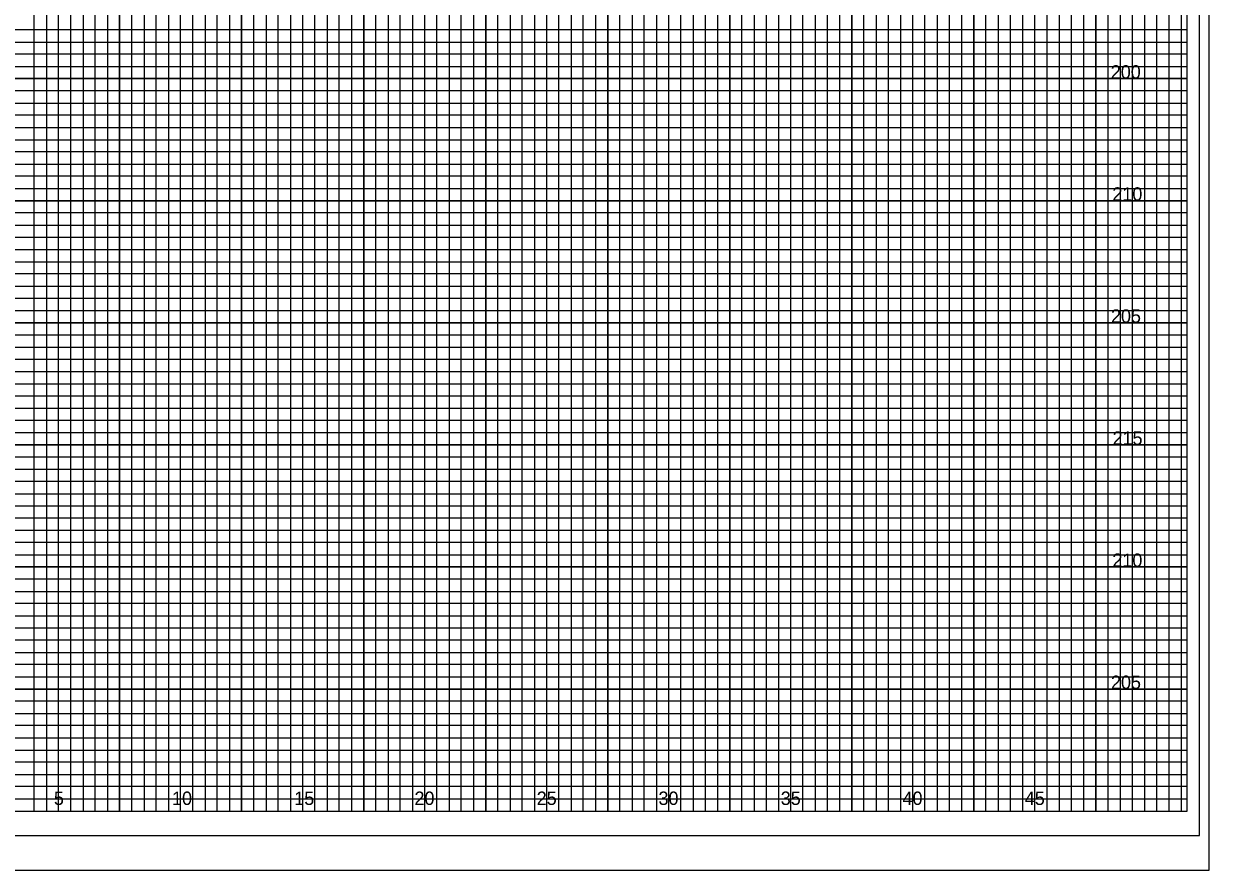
# Model space of a CAD drawing. Extents: x -4 to 103, y -2 to 67.
# Drawn here: x 54.82 to 103.4, y -2.43 to 32.25 of the extents above; entities that cross this region are included whole.
import ezdxf

# ---------------------------------------------------------------- set-up
doc = ezdxf.new("R2010")
doc.units = 0
for name, color, linetype in [('Old_Level_10', 7, 'Continuous'), ('Old_Level_16', 7, 'Continuous'), ('Old_Level_17', 7, 'Continuous'), ('Old_Level_3', 7, 'Continuous'), ('Old_Level_5', 7, 'Continuous'), ('Old_Level_8', 7, 'Continuous'), ('Prop Plan Preparation Sketches Hydraulic Ditch', 7, 'Continuous'), ('Prop XS Dump Level', 7, 'Continuous'), ('Prop XS Finish Grade Pavement', 7, 'Continuous')]:
    doc.layers.add(name, color=color, linetype=linetype)

msp = doc.modelspace()

# ---------------------------------------------------------------- linework, layer by layer
at = {"layer": 'Old_Level_10'}
for p, q in [((56.25, 0), (56.25, 65)), ((58.75, 0), (58.75, 65)), ((61.25, 0), (61.25, 65)), ((63.75, 0), (63.75, 65)), ((66.25, 0), (66.25, 65)), ((68.75, 0), (68.75, 65)), ((71.25, 0), (71.25, 65)), ((73.75, 0), (73.75, 65)), ((91.25, 0), (91.25, 63.425)), ((93.75, 0), (93.75, 63.425)), ((96.25, 0), (96.25, 63.425)), ((98.75, 0), (98.75, 63.425)), ((101.25, 0), (101.25, 63.425)), ((76.25, 0), (76.25, 62)), ((78.75, 0), (78.75, 62)), ((81.25, 0), (81.25, 62)), ((83.75, 0), (83.75, 62)), ((86.25, 0), (86.25, 62)), ((88.75, 0), (88.75, 62)), ((0, 30), (102.5, 30)), ((0, 27.5), (102.5, 27.5)), ((0, 25), (102.5, 25)), ((0, 22.5), (102.5, 22.5)), ((0, 20), (102.5, 20)), ((0, 17.5), (102.5, 17.5)), ((0, 15), (102.5, 15)), ((0, 12.5), (102.5, 12.5)), ((0, 10), (102.5, 10)), ((0, 7.5), (102.5, 7.5)), ((0, 5), (102.5, 5)), ((0, 2.5), (102.5, 2.5))]:
    msp.add_line(p, q, dxfattribs=at)
at = {"layer": 'Old_Level_17'}
msp.add_lwpolyline([(103, 66), (-2.8, 66), (-2.8, -1), (103, -1)], close=True, dxfattribs=at)
at = {"layer": 'Old_Level_3'}
msp.add_line((-3.5, -2.425), (103.4, -2.425), dxfattribs=at)
at = {"layer": 'Old_Level_5'}
msp.add_lwpolyline([(103.4, 67.4), (-3.5, 67.4), (-3.5, -2.425), (103.4, -2.425)], close=True, dxfattribs=at)
at = {"layer": 'Old_Level_8'}
for points in [[(56.25, 0), (56.25, 65)], [(58.75, 65), (58.75, 0), (61.25, 0), (61.25, 65)], [(63.75, 65), (63.75, 0), (66.25, 0), (66.25, 65)], [(68.75, 65), (68.75, 0), (71.25, 0), (71.25, 65)], [(73.75, 65), (73.75, 0), (76.25, 0), (76.25, 62)], [(88.75, 62), (88.75, 0), (91.25, 0), (91.25, 63.425)], [(93.75, 63.425), (93.75, 0), (96.25, 0), (96.25, 63.425)], [(98.75, 63.425), (98.75, 0), (101.25, 0), (101.25, 63.425)], [(78.75, 62), (78.75, 0), (81.25, 0), (81.25, 62)], [(83.75, 62), (83.75, 0), (86.25, 0), (86.25, 62)], [(0, 27.5), (102.5, 27.5), (102.5, 30), (0, 30)], [(0, 22.5), (102.5, 22.5), (102.5, 25), (0, 25)], [(0, 17.5), (102.5, 17.5), (102.5, 20), (0, 20)], [(0, 12.5), (102.5, 12.5), (102.5, 15), (0, 15)], [(0, 7.5), (102.5, 7.5), (102.5, 10), (0, 10)], [(0, 2.5), (102.5, 2.5), (102.5, 5), (0, 5)]]:
    msp.add_lwpolyline(points, dxfattribs=at)
at = {"layer": 'Prop Plan Preparation Sketches Hydraulic Ditch'}
msp.add_lwpolyline([(102.5, 65), (0, 65), (0, 0), (102.5, 0)], close=True, dxfattribs=at)
at = {"layer": 'Prop XS Dump Level'}
for points in [[(54.75, 0), (55.25, 0), (55.25, 65)], [(55.75, 65), (55.75, 0), (56.75, 0), (56.75, 65)], [(57.25, 65), (57.25, 0), (57.75, 0), (57.75, 65)], [(58.25, 65), (58.25, 0), (59.25, 0), (59.25, 65)], [(59.75, 65), (59.75, 0), (60.25, 0), (60.25, 65)], [(60.75, 65), (60.75, 0), (61.75, 0), (61.75, 65)], [(62.25, 65), (62.25, 0), (62.75, 0), (62.75, 65)], [(63.25, 65), (63.25, 0), (64.25, 0), (64.25, 65)], [(64.75, 65), (64.75, 0), (65.25, 0), (65.25, 65)], [(65.75, 65), (65.75, 0), (66.75, 0), (66.75, 65)], [(67.25, 65), (67.25, 0), (67.75, 0), (67.75, 65)], [(68.25, 65), (68.25, 0), (69.25, 0), (69.25, 65)], [(69.75, 65), (69.75, 0), (70.25, 0), (70.25, 65)], [(70.75, 65), (70.75, 0), (71.75, 0), (71.75, 65)], [(72.25, 65), (72.25, 0), (72.75, 0), (72.75, 65)], [(73.25, 65), (73.25, 0), (74.25, 0), (74.25, 62)], [(89.75, 62), (89.75, 0), (90.25, 0), (90.25, 63.425)], [(90.75, 63.425), (90.75, 0), (91.75, 0), (91.75, 63.425)], [(92.25, 63.425), (92.25, 0), (92.75, 0), (92.75, 63.425)], [(93.25, 63.425), (93.25, 0), (94.25, 0), (94.25, 63.425)], [(94.75, 63.425), (94.75, 0), (95.25, 0), (95.25, 63.425)], [(95.75, 63.425), (95.75, 0), (96.75, 0), (96.75, 63.425)], [(97.25, 63.425), (97.25, 0), (97.75, 0), (97.75, 63.425)], [(98.25, 63.425), (98.25, 0), (99.25, 0), (99.25, 63.425)], [(99.75, 63.425), (99.75, 0), (100.25, 0), (100.25, 63.425)], [(100.25, 63.425), (100.75, 63.425), (100.75, 0), (101.75, 0), (101.75, 63.425), (102.25, 63.425), (102.25, 0)], [(74.75, 62), (74.75, 0), (75.25, 0), (75.25, 62)], [(75.75, 62), (75.75, 0), (76.75, 0), (76.75, 62)], [(77.25, 62), (77.25, 0), (77.75, 0), (77.75, 62)], [(78.25, 62), (78.25, 0), (79.25, 0), (79.25, 62)], [(79.75, 62), (79.75, 0), (80.25, 0), (80.25, 62)], [(80.75, 62), (80.75, 0), (81.75, 0), (81.75, 62)], [(82.25, 62), (82.25, 0), (82.75, 0), (82.75, 62)], [(83.25, 62), (83.25, 0), (84.25, 0), (84.25, 62)], [(84.75, 62), (84.75, 0), (85.25, 0), (85.25, 62)], [(85.75, 62), (85.75, 0), (86.75, 0), (86.75, 62)], [(87.25, 62), (87.25, 0), (87.75, 0), (87.75, 62)], [(88.25, 62), (88.25, 0), (89.25, 0), (89.25, 62)], [(0, 31.5), (102.5, 31.5), (102.5, 32), (0, 32)], [(0, 30.5), (102.5, 30.5), (102.5, 31), (0, 31)], [(0, 29), (102.5, 29), (102.5, 29.5), (0, 29.5)], [(0, 28), (102.5, 28), (102.5, 28.5), (0, 28.5)], [(0, 26.5), (102.5, 26.5), (102.5, 27), (0, 27)], [(0, 25.5), (102.5, 25.5), (102.5, 26), (0, 26)], [(0, 24), (102.5, 24), (102.5, 24.5), (0, 24.5)], [(0, 23), (102.5, 23), (102.5, 23.5), (0, 23.5)], [(0, 21.5), (102.5, 21.5), (102.5, 22), (0, 22)], [(0, 20.5), (102.5, 20.5), (102.5, 21), (0, 21)], [(0, 19), (102.5, 19), (102.5, 19.5), (0, 19.5)], [(0, 18), (102.5, 18), (102.5, 18.5), (0, 18.5)], [(0, 16.5), (102.5, 16.5), (102.5, 17), (0, 17)], [(0, 15.5), (102.5, 15.5), (102.5, 16), (0, 16)], [(0, 14), (102.5, 14), (102.5, 14.5), (0, 14.5)], [(0, 13), (102.5, 13), (102.5, 13.5), (0, 13.5)], [(0, 11.5), (102.5, 11.5), (102.5, 12), (0, 12)], [(0, 10.5), (102.5, 10.5), (102.5, 11), (0, 11)], [(0, 9), (102.5, 9), (102.5, 9.5), (0, 9.5)], [(0, 8), (102.5, 8), (102.5, 8.5), (0, 8.5)], [(0, 6.5), (102.5, 6.5), (102.5, 7), (0, 7)], [(0, 5.5), (102.5, 5.5), (102.5, 6), (0, 6)], [(0, 4), (102.5, 4), (102.5, 4.5), (0, 4.5)], [(0, 3), (102.5, 3), (102.5, 3.5), (0, 3.5)], [(0, 1.5), (102.5, 1.5), (102.5, 2), (0, 2)], [(0, 0.5), (102.5, 0.5), (102.5, 1), (0, 1)]]:
    msp.add_lwpolyline(points, dxfattribs=at)

# ---------------------------------------------------------------- texts
at = {"layer": 'Old_Level_16'}
for s, p in [('5', (56.0574, 0.25)), ('10', (60.8971, 0.25)), ('15', (65.9057, 0.25)), ('20', (70.8312, 0.25)), ('25', (75.8399, 0.25)), ('30', (80.8312, 0.25)), ('35', (85.8399, 0.25)), ('40', (90.8313, 0.25)), ('45', (95.8399, 0.25))]:
    msp.add_text(s, height=0.55, dxfattribs=at).set_placement(p)
at = {"layer": 'Prop XS Finish Grade Pavement'}
for s, p in [('200', (99.3638, 30)), ('210', (99.4296, 25)), ('205', (99.3724, 20)), ('215', (99.4383, 15)), ('210', (99.4296, 10)), ('205', (99.3724, 5))]:
    msp.add_text(s, height=0.55, dxfattribs=at).set_placement(p)

doc.saveas('drawing.dxf')
